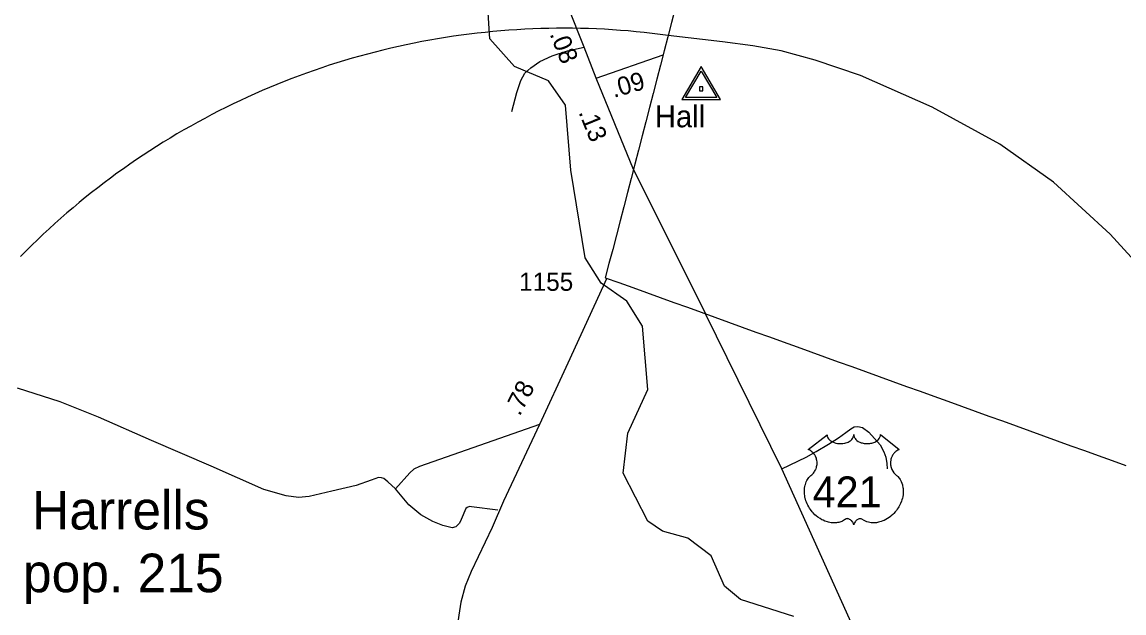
# Model space of a CAD drawing. Extents: x 2093524 to 2270757, y 289120 to 570408.
# Drawn here: x 2236187 to 2243763, y 358011 to 362069 of the extents above; entities that cross this region are included whole.
import ezdxf

# ---------------------------------------------------------------- set-up
doc = ezdxf.new("R2010")
doc.units = 0
for name, color, linetype in [('Exist Boundary Political City Limit New', 7, 'Continuous'), ('Exist Boundary Political CountyLine', 7, 'Continuous'), ('Exist Civil Demographics City Label', 7, 'Continuous'), ('Exist Civil Demographics City Population Label', 7, 'Continuous'), ('Exist Hydrographic Creek Single Shore', 7, 'Continuous'), ('Exist Road Non-System Type 51', 7, 'Continuous'), ('Exist Road Primary US Attributed', 7, 'Continuous'), ('Exist Road Primary US Mileage Hundredths English Label', 7, 'Continuous'), ('Exist Road Primary US Shield CELL', 7, 'Continuous'), ('Exist Road Primary US Shield Number Label', 7, 'Continuous'), ('Exist Road Secondary Mileage Hundredths English Label', 7, 'Continuous'), ('Exist Road Secondary Type 51 Attributed', 7, 'Continuous'), ('Exist Road Secondary Type 51 Number Label', 7, 'Continuous'), ('Exist Survey Geodetic Marker CELL', 7, 'Continuous'), ('Exist Survey Geodetic Marker Label', 7, 'Continuous'), ('Map Preparation Boundary City Limit Buffer Line', 7, 'Continuous')]:
    doc.layers.add(name, color=color, linetype=linetype)

msp = doc.modelspace()

# ---------------------------------------------------------------- linework, layer by layer
at = {"layer": 'Exist Boundary Political City Limit New'}
for points in [[(2240630.2, 361976.8), (2240573.2, 361984.4), (2240518.8, 361991.1), (2240464.2, 361997.1), (2240409.8, 362002.6), (2240355.2, 362007.5), (2240300.5, 362011.9), (2240246, 362015.7), (2240191.2, 362018.8), (2240136.5, 362021.5), (2240081.8, 362023.5), (2240027, 362025), (2239972, 362025.9), (2239917.2, 362026.2), (2239862.5, 362026), (2239807.8, 362025.2), (2239752.8, 362023.8), (2239698, 362021.9), (2239643.2, 362019.3), (2239588.5, 362016.2), (2239534, 362012.5), (2239479.2, 362008.3), (2239424.8, 362003.5), (2239370.2, 361998.1), (2239315.8, 361992.1), (2239261.2, 361985.6), (2239207, 361978.5), (2239152.8, 361970.8), (2239098.5, 361962.6), (2239044.2, 361953.8), (2238990.2, 361944.4), (2238936.5, 361934.4), (2238882.8, 361923.9), (2238829, 361912.9), (2238775.5, 361901.2), (2238722, 361889.1), (2238668.8, 361876.3), (2238615.5, 361863), (2238562.5, 361849.2), (2238509.5, 361834.8), (2238456.8, 361819.8), (2238404.2, 361804.3), (2238351.8, 361788.2), (2238299.8, 361771.6), (2238247.5, 361754.4), (2238195.8, 361736.8), (2238144, 361718.5), (2238092.5, 361699.7), (2238041.2, 361680.4), (2237990.2, 361660.5), (2237939.2, 361640.2), (2237888.8, 361619.2), (2237838.2, 361597.8), (2237788, 361575.8), (2237738, 361553.3), (2237688.2, 361530.3), (2237638.8, 361506.7), (2237589.5, 361482.7), (2237540.5, 361458.1), (2237491.8, 361433), (2237443.2, 361407.4), (2237395.2, 361381.3), (2237347.2, 361354.7), (2237299.5, 361327.6), (2237252.2, 361300), (2237205.2, 361271.9), (2237158.5, 361243.3), (2237112, 361214.2), (2237065.8, 361184.7), (2237020, 361154.7), (2236974.5, 361124.1), (2236929.2, 361093.2), (2236884.2, 361061.7), (2236839.8, 361029.8), (2236795.5, 360997.3), (2236751.8, 360964.5), (2236708.2, 360931.2), (2236665, 360897.4), (2236622.2, 360863.2), (2236579.8, 360828.5), (2236537.8, 360793.4), (2236496, 360757.9), (2236454.5, 360721.9), (2236413.5, 360685.5), (2236373, 360648.6), (2236332.8, 360611.4), (2236293, 360573.7), (2236253.8, 360535.6), (2236214.8, 360497.1), (2236176, 360458.2)], [(2244077.2, 360162.4), (2243668.2, 360612.3), (2243279.2, 360969.9), (2242910, 361231.1), (2242443.5, 361484.6), (2241952.2, 361701), (2241640.2, 361806.1), (2241405.2, 361871), (2241212.2, 361905), (2241002, 361932.8), (2240630.2, 361976.8)]]:
    msp.add_lwpolyline(points, dxfattribs=at)
at = {"layer": 'Exist Boundary Political CountyLine'}
for points in [[(2240678, 362162.6), (2240652.8, 362065.2), (2240627.2, 361967.9), (2240602, 361870.6), (2240576.8, 361773.2), (2240551.5, 361675.9), (2240526.2, 361578.5), (2240500.8, 361481.2), (2240475.5, 361383.8), (2240450.2, 361286.5), (2240425, 361189.2), (2240399.5, 361091.8), (2240374.2, 360994.5), (2240349, 360897.2), (2240323.8, 360799.8), (2240298.5, 360702.5), (2240273, 360605.1), (2240247.8, 360507.8), (2240222.5, 360410.4), (2240197.2, 360313.1), (2240291.2, 360279.2), (2240385.5, 360245.2), (2240479.8, 360211.3), (2240573.8, 360177.3), (2240668, 360143.4), (2240762, 360109.5), (2240856.2, 360075.6), (2240950.2, 360041.6), (2241044.5, 360007.7), (2241138.8, 359973.8), (2241232.8, 359939.8), (2241327, 359905.9), (2241421, 359871.9), (2241515.2, 359838), (2241609.2, 359804.1), (2241703.5, 359770.2), (2241797.5, 359736.2), (2241891.8, 359702.3), (2241986, 359668.3), (2242080, 359634.4), (2242174.2, 359600.5), (2242268.2, 359566.6)], [(2242268.2, 359566.6), (2242362.5, 359532.6), (2242456.5, 359498.7), (2242550.8, 359464.8), (2242645, 359430.8), (2242739, 359396.9), (2242833.2, 359362.9), (2242927.2, 359329), (2243021.5, 359295.1), (2243115.5, 359261.2), (2243209.8, 359227.2), (2243304, 359193.3), (2243398, 359159.3), (2243492.2, 359125.4), (2243586.2, 359091.5), (2243680.5, 359057.6), (2243774.5, 359023.6)]]:
    msp.add_lwpolyline(points, dxfattribs=at)
at = {"layer": 'Exist Hydrographic Creek Single Shore'}
msp.add_lwpolyline([(2241494.2, 357987.1), (2241126.2, 358102.6), (2241017.3, 358193.3), (2240924.2, 358401.8), (2240765.3, 358523), (2240590.2, 358572.5), (2240489.3, 358640), (2240320.3, 358971.4), (2240351.3, 359246.3), (2240490.3, 359545.2), (2240453.2, 359979), (2240344.3, 360151.7), (2240168.2, 360276.5), (2240058.3, 360449.3), (2239961.3, 361051.4), (2239924.2, 361498.2), (2239806.3, 361664.6), (2239572.3, 361764.3), (2239404.1, 361954.6), (2239376.3, 362384.9)], dxfattribs=at)
at = {"layer": 'Exist Road Non-System Type 51'}
for points in [[(2239555.1, 361455.3), (2239587.9, 361585.6), (2239615.4, 361667.7), (2239645, 361717.9), (2239684.4, 361754.2), (2239746.3, 361798.6), (2239831.7, 361837.2), (2239937.6, 361870.2), (2240051.2, 361895.2)], [(2238754.3, 358864), (2238702.1, 358911.2), (2238675.7, 358935), (2238657.7, 358939), (2238637.8, 358940.7), (2238587.9, 358922.4), (2238484.2, 358885.7), (2238316.8, 358846.4), (2238160.9, 358811.1), (2238087, 358804.4), (2238002.9, 358815.9), (2237849, 358858.6), (2237487.7, 359017.6), (2237078.3, 359194), (2236713.1, 359355.1), (2236448.6, 359461), (2236155.9, 359554.4)], [(2239744.4, 359305.8), (2238919.1, 359017.1), (2238881.3, 358996.9), (2238853.6, 358972.5), (2238754.3, 358864)], [(2241410.2, 359001.3), (2241577.4, 359080.6), (2241647, 359119.2), (2241730.7, 359169.7), (2241800.1, 359214.3), (2241849.7, 359250.7), (2241885.6, 359274.9), (2241907.5, 359289.2), (2241933.5, 359291.3), (2241965.5, 359283.8), (2242007.8, 359252.1), (2242086.4, 359164.6), (2242110.8, 359116.9), (2242125.1, 359081.2), (2242131.5, 359037.1), (2242133.7, 359001)], [(2239459.2, 358717.5), (2239277, 358740.1), (2239263.3, 358742), (2239247.1, 358735.8), (2239239.4, 358727.7), (2239206, 358651.7), (2239194.1, 358627.6), (2239170.3, 358601.2), (2239144.2, 358595.1), (2239080.3, 358610.5), (2239011.9, 358638.1), (2238929.8, 358683.4), (2238847.2, 358752.6), (2238754.3, 358864)]]:
    msp.add_lwpolyline(points, dxfattribs=at)
at = {"layer": 'Exist Road Primary US Attributed'}
for points in [[(2240133.8, 361684.1), (2240051.2, 361895.2), (2239939.3, 362177.7), (2239257.5, 363897.9), (2239094.2, 364282.3), (2239077.6, 364354.1), (2239059.2, 364431.9), (2239044.5, 364521.8), (2239004.3, 364807.3), (2238760.3, 366359.2), (2238602.9, 367370.5)], [(2240390.2, 361055.5), (2240133.8, 361684.1)], [(2240390.2, 361055.5), (2240885.7, 360064.9)], [(2242880.4, 355510.6), (2242455.1, 356596.7), (2242151.1, 357362), (2241410.2, 359001.3), (2240885.7, 360064.9)]]:
    msp.add_lwpolyline(points, dxfattribs=at)
at = {"layer": 'Exist Road Primary US Shield CELL'}
msp.add_lwpolyline([(2241721.3, 359234.7), (2241721.7, 359229.4), (2241723, 359223.1), (2241724, 359219.8), (2241726.9, 359213.6), (2241731.8, 359206.2), (2241738.6, 359199), (2241746.3, 359192.7), (2241751.4, 359189.3), (2241760.2, 359184.6), (2241770.1, 359180.4), (2241781.2, 359177.2), (2241792.5, 359175), (2241804.9, 359173.6), (2241817.1, 359173.4), (2241830.4, 359174.4), (2241844.9, 359177.2), (2241851.7, 359178.9), (2241859.2, 359181.5), (2241866.2, 359184.4), (2241873.9, 359188.5), (2241880, 359192.4), (2241884.9, 359195.9), (2241891.7, 359202.5), (2241897.1, 359209.2), (2241899.4, 359213), (2241901.4, 359216.7), (2241904.1, 359224.4), (2241904.8, 359227.9), (2241905.4, 359235), (2241905.8, 359229), (2241906.4, 359225.3), (2241907.4, 359221.6), (2241908.9, 359217.7), (2241911.7, 359212.3), (2241914.7, 359207.7), (2241920.4, 359201), (2241924, 359197.6), (2241927.3, 359194.9), (2241936, 359188.9), (2241946.2, 359183.8), (2241951.2, 359181.6), (2241956.4, 359179.8), (2241962.9, 359177.8), (2241969.7, 359176.2), (2241976.4, 359175), (2241983.2, 359174.1), (2241990.2, 359173.5), (2241995.9, 359173.4), (2242002.9, 359173.4), (2242009.3, 359173.8), (2242015.9, 359174.6), (2242023.2, 359175.8), (2242029.1, 359177.1), (2242036.8, 359179.1), (2242043.8, 359181.7), (2242050, 359184.3), (2242057.9, 359188.5), (2242064.4, 359192.5), (2242069.1, 359196.3), (2242074.7, 359201.5), (2242080, 359207.6), (2242083.2, 359212.1), (2242085.4, 359216.8), (2242087.4, 359221.6), (2242088.7, 359226.8), (2242089.3, 359231.3), (2242089.4, 359235.1), (2242218, 359132.7), (2242215, 359131.5), (2242208, 359128.1), (2242202.4, 359124.8), (2242193.6, 359118.6), (2242189.8, 359115.2), (2242186, 359111.6), (2242182.5, 359107.8), (2242179.4, 359104.2), (2242175.7, 359099.1), (2242172.4, 359093.9), (2242169.1, 359088.2), (2242166.7, 359083.2), (2242162.7, 359072.9), (2242160.8, 359066.4), (2242159.6, 359060.8), (2242158.1, 359049.4), (2242157.7, 359043.9), (2242157.7, 359038.5), (2242158, 359032.8), (2242158.6, 359027.3), (2242159.6, 359021.6), (2242160.5, 359016.6), (2242162.1, 359010.5), (2242164.3, 359003.3), (2242167.2, 358996.4), (2242173, 358985.2), (2242180.6, 358973.8), (2242186, 358967.4), (2242191.3, 358962), (2242199.2, 358955.3), (2242203.5, 358951.5), (2242208.5, 358946.5), (2242216.5, 358937.2), (2242219.8, 358932.8), (2242223.1, 358927.9), (2242226.1, 358922.8), (2242229.2, 358917.3), (2242231.6, 358912.5), (2242236.1, 358901.5), (2242239.4, 358890.8), (2242240.9, 358885.1), (2242243.3, 358872.5), (2242244.2, 358866.3), (2242245.2, 358854), (2242245.3, 358839.1), (2242244.1, 358825), (2242241.5, 358808.5), (2242239.3, 358798.6), (2242235.9, 358787.1), (2242232.6, 358777.2), (2242226.7, 358762.5), (2242221.5, 358751.9), (2242214.8, 358739.4), (2242210.1, 358731.9), (2242204.7, 358723.8), (2242198, 358714.6), (2242190.1, 358704.7), (2242180.6, 358694.3), (2242172.9, 358686.6), (2242162.9, 358677.6), (2242156.8, 358672.6), (2242148.2, 358666.1), (2242136.3, 358658.2), (2242124.6, 358651.4), (2242114.7, 358646.3), (2242105.9, 358642.5), (2242094.5, 358638.2), (2242075.5, 358632.9), (2242068.6, 358631.5), (2242060.4, 358630.3), (2242052.7, 358629.5), (2242045.3, 358629.1), (2242035.2, 358629.1), (2242025.3, 358629.8), (2242015.9, 358631.2), (2242006.1, 358633.3), (2241995.8, 358636.3), (2241986.5, 358639.9), (2241977.1, 358644.6), (2241961.2, 358654.6), (2241956.6, 358657), (2241954, 358657.7), (2241947.9, 358658), (2241942.1, 358656.8), (2241936.2, 358654.5), (2241932.6, 358652.6), (2241927.8, 358649.4), (2241924.2, 358646.6), (2241919.8, 358642.4), (2241916.8, 358638.9), (2241914.4, 358636.1), (2241910, 358629.1), (2241908.4, 358625.7), (2241906.7, 358621.4), (2241905.2, 358615), (2241903.2, 358623.1), (2241900.8, 358628.4), (2241898.1, 358632.9), (2241895.3, 358637), (2241890.8, 358642.1), (2241886.8, 358646), (2241881.9, 358650), (2241876.7, 358653.1), (2241872.6, 358655.2), (2241868.8, 358656.7), (2241864.2, 358657.8), (2241860.4, 358658.1), (2241857.3, 358658), (2241853, 358657), (2241847.2, 358652.9), (2241841.6, 358649.1), (2241835.6, 358645.3), (2241828.5, 358641.5), (2241823.3, 358639.1), (2241817, 358636.7), (2241809.7, 358634.2), (2241801.8, 358632.2), (2241793.7, 358630.6), (2241786.6, 358629.5), (2241778.9, 358628.8), (2241772, 358628.5), (2241764.8, 358628.6), (2241758, 358629.1), (2241750.2, 358629.8), (2241740.5, 358631.3), (2241732.4, 358633.1), (2241723.9, 358635.4), (2241715.2, 358638.1), (2241705.9, 358641.7), (2241694.2, 358646.8), (2241686, 358651), (2241673.2, 358658.3), (2241658.2, 358668.7), (2241646.8, 358677.9), (2241638.5, 358685.5), (2241626.3, 358697.9), (2241619.1, 358706), (2241607.8, 358720.6), (2241600.6, 358731.2), (2241595.9, 358738.9), (2241589.1, 358751.4), (2241585.3, 358759.2), (2241580.5, 358770.6), (2241576.6, 358781), (2241573.4, 358790.9), (2241571.7, 358797.2), (2241569.3, 358808.2), (2241567.8, 358816.1), (2241566.4, 358826.8), (2241565.6, 358838.1), (2241565.4, 358848.5), (2241565.7, 358857.2), (2241566.7, 358867.3), (2241568.4, 358878), (2241570.4, 358887.2), (2241572.3, 358893.8), (2241575, 358901.9), (2241578.6, 358910.8), (2241582.9, 358919.3), (2241587, 358926.3), (2241592, 358933.9), (2241597.1, 358940.4), (2241603.6, 358947.5), (2241610.5, 358954.1), (2241616.7, 358959.2), (2241624.2, 358966.5), (2241628.1, 358970.9), (2241632.7, 358977), (2241636.4, 358982.7), (2241639.4, 358987.8), (2241643.3, 358995.3), (2241645.7, 359001), (2241648.6, 359009.6), (2241650.1, 359015.7), (2241651.6, 359023.5), (2241652.6, 359030.9), (2241653, 359040.1), (2241652.8, 359047.7), (2241651.8, 359056.6), (2241650.1, 359065.1), (2241648.1, 359072.5), (2241644.9, 359081), (2241642, 359087.3), (2241637.1, 359095.7), (2241631.6, 359103.5), (2241625.9, 359109.9), (2241620.2, 359115.6), (2241614.8, 359119.9), (2241609.6, 359123.6), (2241603, 359127.5), (2241596.7, 359130.7), (2241592.8, 359132.3)], close=True, dxfattribs=at)
at = {"layer": 'Exist Road Secondary Type 51 Attributed'}
msp.add_line((2240133.8, 361684.1), (2240595.2, 361844.2), dxfattribs=at)
msp.add_lwpolyline([(2240207.7, 360309.3), (2239938.8, 359727.1), (2239744.4, 359305.8), (2239498.1, 358777.3), (2239419.4, 358597.2), (2239274.2, 358295.9), (2239234.5, 358193.8), (2239204.5, 358084.5), (2239191.3, 357995.7), (2239176.1, 357899.8), (2239176.8, 357819.8), (2239192.5, 357670.3), (2239212.9, 357575.5), (2239240.5, 357485.4), (2239277, 357402.9), (2239323.8, 357311.1), (2239364.8, 357251.3), (2239418.8, 357172.1), (2239483.7, 357102.4), (2239565.3, 357023.8), (2239674.6, 356944.5), (2239729.8, 356906.1), (2239861.9, 356846.1), (2239945.7, 356819.3)], dxfattribs=at)
at = {"layer": 'Exist Survey Geodetic Marker CELL'}
for points in [[(2240990.1, 361537.9), (2240856.2, 361763.9), (2240722.7, 361537.9)], [(2240964.2, 361550), (2240748.7, 361550), (2240856.2, 361732.1)], [(2240868.5, 361596.6), (2240868.5, 361624.8), (2240844.2, 361624.8), (2240844.2, 361596.6)]]:
    msp.add_lwpolyline(points, close=True, dxfattribs=at)
at = {"layer": 'Map Preparation Boundary City Limit Buffer Line'}
for points in [[(2240630.2, 361976.8), (2240573.2, 361984.4), (2240518.8, 361991.1), (2240464.2, 361997.1), (2240409.8, 362002.6), (2240355.2, 362007.5), (2240300.5, 362011.9), (2240246, 362015.7), (2240191.2, 362018.8), (2240136.5, 362021.5), (2240081.8, 362023.5), (2240027, 362025), (2239972, 362025.9), (2239917.2, 362026.2), (2239862.5, 362026), (2239807.8, 362025.2), (2239752.8, 362023.8), (2239698, 362021.9), (2239643.2, 362019.3), (2239588.5, 362016.2), (2239534, 362012.5), (2239479.2, 362008.3), (2239424.8, 362003.5), (2239370.2, 361998.1), (2239315.8, 361992.1), (2239261.2, 361985.6), (2239207, 361978.5), (2239152.8, 361970.8), (2239098.5, 361962.6), (2239044.2, 361953.8), (2238990.2, 361944.4), (2238936.5, 361934.4), (2238882.8, 361923.9), (2238829, 361912.9), (2238775.5, 361901.2), (2238722, 361889.1), (2238668.8, 361876.3), (2238615.5, 361863), (2238562.5, 361849.2), (2238509.5, 361834.8), (2238456.8, 361819.8), (2238404.2, 361804.3), (2238351.8, 361788.2), (2238299.8, 361771.6), (2238247.5, 361754.4), (2238195.8, 361736.8), (2238144, 361718.5), (2238092.5, 361699.7), (2238041.2, 361680.4), (2237990.2, 361660.5), (2237939.2, 361640.2), (2237888.8, 361619.2), (2237838.2, 361597.8), (2237788, 361575.8), (2237738, 361553.3), (2237688.2, 361530.3), (2237638.8, 361506.7), (2237589.5, 361482.7), (2237540.5, 361458.1), (2237491.8, 361433), (2237443.2, 361407.4), (2237395.2, 361381.3), (2237347.2, 361354.7), (2237299.5, 361327.6), (2237252.2, 361300), (2237205.2, 361271.9), (2237158.5, 361243.3), (2237112, 361214.2), (2237065.8, 361184.7), (2237020, 361154.7), (2236974.5, 361124.1), (2236929.2, 361093.2), (2236884.2, 361061.7), (2236839.8, 361029.8), (2236795.5, 360997.3), (2236751.8, 360964.5), (2236708.2, 360931.2), (2236665, 360897.4), (2236622.2, 360863.2), (2236579.8, 360828.5), (2236537.8, 360793.4), (2236496, 360757.9), (2236454.5, 360721.9), (2236413.5, 360685.5), (2236373, 360648.6), (2236332.8, 360611.4), (2236293, 360573.7), (2236253.8, 360535.6), (2236214.8, 360497.1), (2236176, 360458.2)], [(2244077.2, 360162.4), (2243668.2, 360612.3), (2243279.2, 360969.9), (2242910, 361231.1), (2242443.5, 361484.6), (2241952.2, 361701), (2241640.2, 361806.1), (2241405.2, 361871), (2241212.2, 361905), (2241002, 361932.8), (2240630.2, 361976.8)]]:
    msp.add_lwpolyline(points, dxfattribs=at)

# ---------------------------------------------------------------- texts
at = {"layer": 'Exist Civil Demographics City Label'}
msp.add_text('Harrells', height=265, dxfattribs=at).set_placement((2236256.7, 358584.1))
at = {"layer": 'Exist Civil Demographics City Population Label'}
msp.add_text('pop. 215', height=265, dxfattribs=at).set_placement((2236193.6, 358152.8))
at = {"layer": 'Exist Road Primary US Mileage Hundredths English Label'}
for s, rotation, p in [('.08', 291.61974, (2239813.1, 361987.2)), ('.13', 292.18983, (2240011.4, 361449.2))]:
    msp.add_text(s, height=125, rotation=rotation, dxfattribs=at).set_placement(p)
at = {"layer": 'Exist Road Primary US Shield Number Label'}
msp.add_text('421', height=212.5, dxfattribs=at).set_placement((2241622.5, 358735.4))
at = {"layer": 'Exist Road Secondary Mileage Hundredths English Label'}
for s, rotation, p in [('.09', 15.85208, (2240255.6, 361547.8)), ('.78', 62.60063, (2239608.5, 359356.9))]:
    msp.add_text(s, height=125, rotation=rotation, dxfattribs=at).set_placement(p)
at = {"layer": 'Exist Road Secondary Type 51 Number Label'}
msp.add_text('1155', height=125, dxfattribs=at).set_placement((2239604.8, 360222.9))
at = {"layer": 'Exist Survey Geodetic Marker Label'}
msp.add_text('Hall', height=150, dxfattribs=at).set_placement((2240537.8, 361345.9))

doc.saveas('drawing.dxf')
